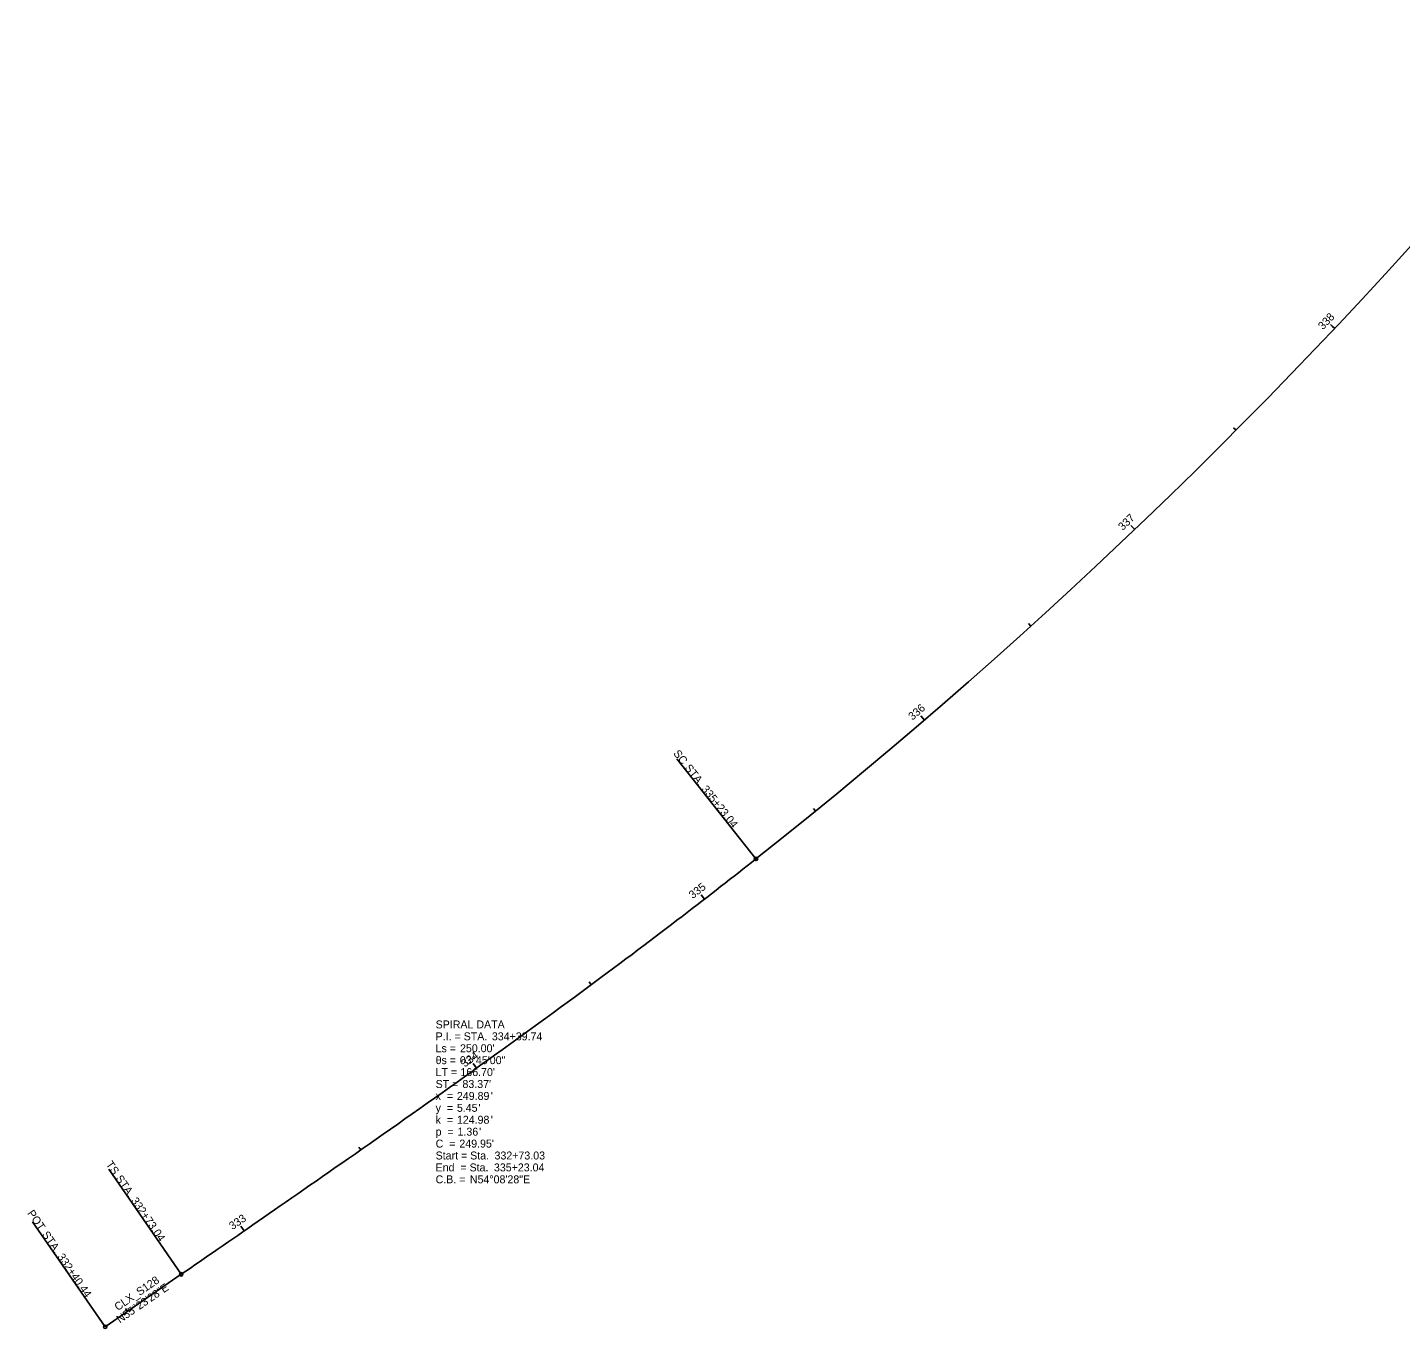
# Model space of a CAD drawing. Extents: x 1380776 to 1381901, y 503546 to 507267.
# Drawn here: x 1380776.3 to 1381260.3, y 503546 to 504004.6 of the extents above; entities that cross this region are included whole.
import ezdxf

# ---------------------------------------------------------------- set-up
doc = ezdxf.new("R2010")
doc.units = 0
for name, color, linetype in [('_CIVIL_CONSTRUCTION', 7, 'Continuous'), ('DR_P_Storm_Sewer', 7, 'Continuous'), ('DR_X_Cells', 7, 'Continuous'), ('DR_X_Storm_Sewer', 7, 'Continuous'), ('GK_Drainage_Nodes', 7, 'Continuous'), ('SC_Scratch1', 7, 'Continuous'), ('SC_Scratch3', 7, 'Continuous')]:
    doc.layers.add(name, color=color, linetype=linetype)

msp = doc.modelspace()

# ---------------------------------------------------------------- linework, layer by layer
at = {"layer": '_CIVIL_CONSTRUCTION'}
for p, q in [((1381237.07, 503898.56), (1381236.2, 503899.38)), ((1381166.58, 503827.65), (1381165.75, 503828.51)), ((1381092.47, 503760.52), (1381091.69, 503761.43)), ((1381033.1, 503711.56), (1381005.17, 503746.85)), ((1381014.95, 503697.37), (1381013.73, 503698.95)), ((1380934.61, 503637.84), (1380933.91, 503638.81)), ((1380830.52, 503565.14), (1380804.96, 503602.18)), ((1380803.7, 503546.63), (1380778.14, 503583.67)), ((1380852.71, 503580.46), (1380852.03, 503581.45))]:
    msp.add_line(p, q, dxfattribs=at)
for centre in [(1381033.1, 503711.56), (1380830.52, 503565.14), (1380803.7, 503546.63)]:
    msp.add_circle(centre, 0.6, dxfattribs=at)
at = {"layer": 'DR_P_Storm_Sewer'}
for p, q in [((1381033.1, 503711.56), (1381005.17, 503746.85)), ((1381014.95, 503697.37), (1381014.22, 503698.32)), ((1380830.52, 503565.14), (1380804.96, 503602.18)), ((1380803.7, 503546.63), (1380778.14, 503583.67))]:
    msp.add_line(p, q, dxfattribs=at)
for centre in [(1381033.1, 503711.56), (1380830.52, 503565.14), (1380803.7, 503546.63)]:
    msp.add_circle(centre, 0.6, dxfattribs=at)
at = {"layer": 'DR_X_Storm_Sewer'}
for p, q in [((1381237.07, 503898.56), (1381235.62, 503899.93)), ((1381202.29, 503862.64), (1381201.44, 503863.49)), ((1381166.58, 503827.65), (1381165.2, 503829.09)), ((1381129.96, 503793.6), (1381129.16, 503794.49)), ((1381092.47, 503760.52), (1381091.17, 503762.04)), ((1381033.1, 503711.56), (1381005.17, 503746.85)), ((1381054.12, 503728.44), (1381053.36, 503729.37)), ((1381014.95, 503697.37), (1381013.73, 503698.95)), ((1380975.06, 503667.23), (1380974.34, 503668.2)), ((1380934.61, 503637.84), (1380933.45, 503639.46)), ((1380893.77, 503608.98), (1380893.09, 503609.97)), ((1380830.52, 503565.14), (1380804.96, 503602.18)), ((1380803.7, 503546.63), (1380778.14, 503583.67)), ((1380852.71, 503580.46), (1380851.57, 503582.1)), ((1380811.57, 503552.06), (1380810.88, 503553.05))]:
    msp.add_line(p, q, dxfattribs=at)
for centre in [(1381033.1, 503711.56), (1380830.52, 503565.14), (1380803.7, 503546.63)]:
    msp.add_circle(centre, 0.6, dxfattribs=at)
at = {"layer": 'SC_Scratch1'}
msp.add_line((1380803.7, 503546.63), (1380830.53, 503565.15), dxfattribs=at)
msp.add_arc((1379847.87, 505209.16), 1909.86, 308.35888, 354.62505, dxfattribs=at)
msp.add_arc((1379847.87, 505209.16), 1909.86, 308.35888, 354.62505, dxfattribs=at)
msp.add_open_spline([(1380830.52, 503565.14), (1380839.1, 503571.06), (1380856.24, 503582.89), (1380890.49, 503606.63), (1380933.11, 503636.56), (1380975.24, 503667.18), (1381008.49, 503692.3), (1381024.93, 503705.1), (1381033.1, 503711.56)], degree=3, dxfattribs=at)
msp.add_open_spline([(1380830.52, 503565.14), (1380839.1, 503571.06), (1380856.24, 503582.89), (1380890.49, 503606.63), (1380933.11, 503636.56), (1380975.24, 503667.18), (1381008.49, 503692.3), (1381024.93, 503705.1), (1381033.1, 503711.56)], degree=3, dxfattribs=at)

# ---------------------------------------------------------------- texts
at = {"layer": '_CIVIL_CONSTRUCTION'}
for s, rotation, p in [('SC', 308.3589, (1381003.8, 503748.66)), (' STA. ', 308.3589, (1381007.17, 503744.4)), ('335+23.04', 308.3589, (1381013.73, 503736.11)), ('335', 37.6995, (1381010.78, 503697.36)), ('TS', 304.6089, (1380803.83, 503603.9)), (' STA. ', 304.6089, (1380806.67, 503599.79)), ('332+73.04', 304.6089, (1380812.68, 503591.08)), ('POT', 304.6089, (1380776.14, 503586.64)), (' STA. ', 304.6089, (1380780.71, 503580.02)), ('332+40.44', 304.6089, (1380786.72, 503571.32)), ('CLX_S128', 34.6089, (1380808.18, 503552.15)), ('N55°23\'28"E', 34.6089, (1380808.9, 503547.79))]:
    msp.add_text(s, height=2.8, rotation=rotation, dxfattribs=at).set_placement(p)
at = {"layer": 'DR_P_Storm_Sewer'}
for s, rotation, p in [('SC', 308.3589, (1381003.8, 503748.66)), (' STA. ', 308.3589, (1381007.17, 503744.4)), ('335+23.04', 308.3589, (1381013.73, 503736.11)), ('TS', 304.6089, (1380803.83, 503603.9)), (' STA. ', 304.6089, (1380806.67, 503599.79)), ('332+73.04', 304.6089, (1380812.68, 503591.08)), ('POT', 304.6089, (1380776.14, 503586.64)), (' STA. ', 304.6089, (1380780.71, 503580.02)), ('332+40.44', 304.6089, (1380786.72, 503571.32)), ('CLX_S128', 34.6089, (1380808.18, 503552.15)), ('N55°23\'28"E', 34.6089, (1380808.9, 503547.79))]:
    msp.add_text(s, height=2.8, rotation=rotation, dxfattribs=at).set_placement(p)
at = {"layer": 'DR_X_Cells'}
for s, p in [('SPIRAL DATA', (1380920.18, 503651.82)), ('P.I. = STA. ', (1380920.18, 503647.62)), ('334+39.74', (1380940, 503647.62)), ('Ls = ', (1380920.18, 503643.42)), ("250.00'", (1380928.77, 503643.42)), ('θs = ', (1380920.18, 503639.22)), ('03°45\'00"', (1380928.72, 503639.22)), ('ST = ', (1380920.18, 503630.82)), ('LT = ', (1380920.18, 503635.02)), ("166.70'", (1380928.92, 503635.02)), ("83.37'", (1380929.64, 503630.82)), ('x  = ', (1380920.18, 503626.62)), ('249.89', (1380927.68, 503626.62)), ("'", (1380939.64, 503626.62)), ('y  = ', (1380920.18, 503622.42)), ('5.45', (1380927.68, 503622.42)), ("'", (1380935.29, 503622.42)), ('k  = ', (1380920.18, 503618.22)), ('124.98', (1380927.68, 503618.22)), ("'", (1380939.64, 503618.22)), ('p  = ', (1380920.18, 503614.02)), ('1.36', (1380927.9, 503614.02)), ("'", (1380935.51, 503614.02)), ('C  = ', (1380920.18, 503609.82)), ("249.95'", (1380928.55, 503609.82)), ('Start = Sta. ', (1380920.18, 503605.62)), ('332+73.03', (1380940.94, 503605.62)), ('C.B. = ', (1380920.18, 503597.22)), ('End  = Sta. ', (1380920.18, 503601.42)), ('N54°08\'28"E', (1380932.25, 503597.22)), ('335+23.04', (1380940.73, 503601.42))]:
    msp.add_text(s, height=2.8, dxfattribs=at).set_placement(p)
at = {"layer": 'DR_X_Storm_Sewer'}
for s, rotation, p in [('338', 46.6677, (1381232.94, 503897.87)), ('337', 43.6677, (1381162.35, 503827.13)), ('336', 40.6677, (1381088.26, 503760.26)), ('SC', 308.3589, (1381003.8, 503748.66)), (' STA. ', 308.3589, (1381007.17, 503744.4)), ('335+23.04', 308.3589, (1381013.73, 503736.11)), ('335', 37.6995, (1381010.78, 503697.36)), ('334', 35.576, (1380930.47, 503638)), ('TS', 304.6089, (1380803.83, 503603.9)), (' STA. ', 304.6089, (1380806.67, 503599.79)), ('332+73.04', 304.6089, (1380812.68, 503591.08)), ('POT', 304.6089, (1380776.14, 503586.64)), ('333', 34.6525, (1380848.57, 503580.69)), (' STA. ', 304.6089, (1380780.71, 503580.02)), ('332+40.44', 304.6089, (1380786.72, 503571.32)), ('CLX_S128', 34.6089, (1380808.18, 503552.15)), ('N55°23\'28"E', 34.6089, (1380808.9, 503547.79))]:
    msp.add_text(s, height=2.8, rotation=rotation, dxfattribs=at).set_placement(p)
at = {"layer": 'GK_Drainage_Nodes'}
for s, p in [('SPIRAL DATA', (1380920.18, 503651.82)), ('P.I. = STA. ', (1380920.18, 503647.62)), ('334+39.74', (1380940, 503647.62)), ('Ls = ', (1380920.18, 503643.42)), ("250.00'", (1380928.77, 503643.42)), ('θs = ', (1380920.18, 503639.22)), ('03°45\'00"', (1380928.72, 503639.22)), ('ST = ', (1380920.18, 503630.82)), ('LT = ', (1380920.18, 503635.02)), ("166.70'", (1380928.92, 503635.02)), ("83.37'", (1380929.64, 503630.82)), ('x  = ', (1380920.18, 503626.62)), ('249.89', (1380927.68, 503626.62)), ("'", (1380939.64, 503626.62)), ('y  = ', (1380920.18, 503622.42)), ('5.45', (1380927.68, 503622.42)), ("'", (1380935.29, 503622.42)), ('k  = ', (1380920.18, 503618.22)), ('124.98', (1380927.68, 503618.22)), ("'", (1380939.64, 503618.22)), ('p  = ', (1380920.18, 503614.02)), ('1.36', (1380927.9, 503614.02)), ("'", (1380935.51, 503614.02)), ('C  = ', (1380920.18, 503609.82)), ("249.95'", (1380928.55, 503609.82)), ('Start = Sta. ', (1380920.18, 503605.62)), ('332+73.03', (1380940.94, 503605.62)), ('C.B. = ', (1380920.18, 503597.22)), ('End  = Sta. ', (1380920.18, 503601.42)), ('N54°08\'28"E', (1380932.25, 503597.22)), ('335+23.04', (1380940.73, 503601.42))]:
    msp.add_text(s, height=2.8, dxfattribs=at).set_placement(p)
at = {"layer": 'SC_Scratch3'}
for s, p in [('SPIRAL DATA', (1380920.18, 503651.82)), ('P.I. = STA. ', (1380920.18, 503647.62)), ('334+39.74', (1380940, 503647.62)), ('Ls = ', (1380920.18, 503643.42)), ("250.00'", (1380928.77, 503643.42)), ('θs = ', (1380920.18, 503639.22)), ('03°45\'00"', (1380928.72, 503639.22)), ('ST = ', (1380920.18, 503630.82)), ('LT = ', (1380920.18, 503635.02)), ("166.70'", (1380928.92, 503635.02)), ("83.37'", (1380929.64, 503630.82)), ('x  = ', (1380920.18, 503626.62)), ('249.89', (1380927.68, 503626.62)), ("'", (1380939.64, 503626.62)), ('y  = ', (1380920.18, 503622.42)), ('5.45', (1380927.68, 503622.42)), ("'", (1380935.29, 503622.42)), ('k  = ', (1380920.18, 503618.22)), ('124.98', (1380927.68, 503618.22)), ("'", (1380939.64, 503618.22)), ('p  = ', (1380920.18, 503614.02)), ('1.36', (1380927.9, 503614.02)), ("'", (1380935.51, 503614.02)), ('C  = ', (1380920.18, 503609.82)), ("249.95'", (1380928.55, 503609.82)), ('Start = Sta. ', (1380920.18, 503605.62)), ('332+73.03', (1380940.94, 503605.62)), ('C.B. = ', (1380920.18, 503597.22)), ('End  = Sta. ', (1380920.18, 503601.42)), ('N54°08\'28"E', (1380932.25, 503597.22)), ('335+23.04', (1380940.73, 503601.42))]:
    msp.add_text(s, height=2.8, dxfattribs=at).set_placement(p)

doc.saveas('drawing.dxf')
